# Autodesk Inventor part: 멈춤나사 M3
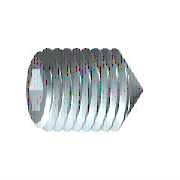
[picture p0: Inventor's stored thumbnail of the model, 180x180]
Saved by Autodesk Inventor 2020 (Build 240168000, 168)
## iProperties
Created: 2012-02
Part Number: 멈춤나사 M3
Material: 강철, 연강
Description: 6각 소켓 머리 없는 멈춤 나사
Document SubType Name: Modeling
Standard: KS B 1028
Designer: mduedu
Standards Organization: KS
Language: ko-KR
Size Designation: 원추점 M3x8
Categories: <MemberInstance><Categories><Category DisplayName="조임쇠" InternalName="e4da775c-781d-43d5-af7c-5136215cf5a6" Mnemonic="FSTN"><Category DisplayName="볼트" InternalN
Density: 7.86 g/cm^3
Mass: 0.360339 g
Surface Area: 0.888172 cm^2
Volume: 0.0458447 cm^3
Appearance: 강철
IsCustomPart: 1
Author: mduedu
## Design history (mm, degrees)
sketch "스케치1"
  geometry: L1 (0, 0)-(5.5, 0); L2 (8, 0.866)-(8, 1.5); L3 (8, 1.5)-(0, 1.5); L4 (8, 0.866)-(6, 0.866); L5 (6, 0.866)-(5.5, 0); L6 (0, -0.3)-(0, 1.8) reference; L7 (0, 1.5)-(0, 0)
  constraints: 13 end point, 3 parallel, 1 collinear, 1 perpendicular, 1 point on line
  dimensions: "d0" = 2 distance of L2.start L4.end (= INTI); "d1" = 60 deg angle of L5 L1; "d2" = 3 diameter of L3 L1 (= NND); "d3" = 1.73205 diameter of L4 L1 (= 1.1547 x SW); "d5" = 8 distance from line of L2 L3.end (= NLG)
revolve "본체" sketch "스케치1" stored, may be unused: angle "d6" = 90 deg
sketch "스케치2"
  geometry: L1 (-0.433, 0.75)-(0.433, 0.75); L2 (0.433, 0.75)-(0.866, 0); L3 (0.866, 0)-(0.433, -0.75); L4 (0.433, -0.75)-(-0.433, -0.75); L5 (-0.433, -0.75)-(-0.866, 0); L6 (-0.866, 0)-(-0.433, 0.75); 3 further points
  constraints: 12 end point, 1 coincident, 1 horizontal, 13 other
extrude "슬롯" join sketch "스케치2" taper "d7" = 0 deg; stored distance "d21" = 10
workaxis "Work Axis1"
workplane "Work Plane1"
sketch "스케치5"
  geometry: L1 (-4, -0.15)-(-2.65, -1.5) reference; L2 (-4, 0.15)-(-2.65, 1.5) reference; L3 (-2.65, 1.5)-(-4.15, 0); L4 (-2.65, -1.5)-(-4.15, 0); 1 further point
  constraints: 4 end point, 1 horizontal alignment, 1 perpendicular
node "작업점1"
node "작업축2"
body "Solid1"
feature "스레드" dims "d12" = 8 (= NLG), "d13" = 0
chamfer "모따기1" distance "d8" = 1.35 (computed from NND, SPD, FAWI); stored, may be unused: angle "d9" = 45 deg (= FAWI), second distance "d34" = 1.35 (computed from NND, SPD, FAWI)
chamfer "모따기2" distance "d10" = 0.30673 (= -0.5 x GD1 + 0.5 x NND); stored, may be unused: angle "d11" = 45 deg (= FAWI), second distance "d35" = 0.30673 (= -0.5 x GD1 + 0.5 x NND)
other parameters: "NND" = 3 [user parameter; used in 5 equation terms], "NLG" = 8 [user parameter; used in 2 equation terms], "INTI" = 2 [user parameter; used in 1 equation term], "FAWI" = 45 deg [user parameter; used in 4 equation terms], "SW" = 1.5 [user parameter; used in 2 equation terms], "GD1" = 2.38655 (= THREADDIA - 1.2269 x PTC) [user parameter; used in 2 equation terms], "d4" = 0, "FAWI1" = 45 deg [user parameter], "SPD" = 0.3 [user parameter; used in 2 equation terms], "d36" = 0, "d37" = 0, "GUL" = 0.30673 (= 0.61345 x PTC) [user parameter], "TOA" = 30 deg [user parameter], "THREADDIA" = 3 [user parameter; used in 1 equation term], "PTC" = 0.5 [user parameter; used in 4 equation terms], "GAL" = 0.30673 (= 0.61345 x PTC) [user parameter], "E0" = 1.7325 (= 1.155 x SW) [user parameter]
